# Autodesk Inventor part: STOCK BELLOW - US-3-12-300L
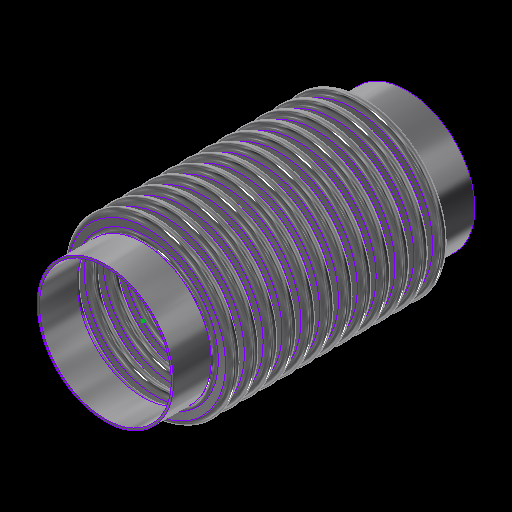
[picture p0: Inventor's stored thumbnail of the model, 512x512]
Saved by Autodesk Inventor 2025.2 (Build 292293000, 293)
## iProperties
Category: 22 GA (0.030 THICK)
RuleStatus: InUse
Created: 2024-01
Part Number: STOCK BELLOW - US-3-12-300L
Project: =STOCK BELLOWS: <Stock Number><SFILL>
Material: ASTM A240-304
Description: =STOCK BELLOWS: <Stock Number>, <SID_> I.D., <SOD_> O.D., <SPLY_> PLY, <Category>, <SNET_CONS> CONS.<PITCH_><STANGENT_> TANGENT<SFILL>
Document SubType Name: Sheet Metal
Designer: GS
Stock Number: U.S-3-12-300L
Surface Area: 2582.18 cm^2
Volume: 194.783 cm^3
Sheet Metal Rule: Default
Appearance: STAINLESS STEEL
Mass: 1569.42 g
Density: 8.05729 g/cm^3
THK: 0.036
ID: 3.500
OD: 4.250
CONS_: 2
PITCH: 0.500
TANGENT: 0.500
BELLOWS_UPSET: 0.000
d79: 1.000
d82: 1.000
d83: 26.000
d84: 24.000
d174: 8
d214: 8
STHK_: 0.030
SID_: 3.500
SOD_: 4.500
SPITCH_: 0.500
STANGENT__: 1.000
SBELLOWS_UPSET_: 0.000
SDIFF_TAN: 1.000
d252: 2
d275: 2
d287: 0.050
d289: 0.500
d290: 0.000
SOD_NECK: 3 5/8
PLY: 1
PSET: 4.178
PBAR: 1.035
COUNTER: 1.500
NET_TUBE: 3.071
CONS: 2
S_CONS: 0
NET_CONS: 2
ID_M: 88.90 mm
OD_M: 107.95 mm
THK_M: 0.91 mm
ID_U: 3.500 in
OD_U: 4.250 in
THK_U: 0.036 in
TANGENT2: 0.500
TAN_TO_TAN: 1.000 in
d80: 2.571
d81: 10
SID: 2.375
SCONS_: 12
SPITCH: 0.250
STANGENT_: 1.000
SBELLOWS_UPSET: 0.000
SNET_CONS: 12
SS_CONS: 0
SCONS: 8
d190: 8
d191: 1
d192: 1
d193: 8
d194: 0
SIZE: 3.00
PRESSURE: 300
d230: 8
STANGENT: 4.000
SPLY_: 2
d233: 8
d234: 0
d263: 2
d265: 1
d268: 2
d269: 0
d286: 2
d288: 1
d291: 2
d292: 0
SREROLL: 0.750
BLETP: 1.000 ul
PRES_Copy: 85
MATTABLE: 20 GA (0.036 THICK)
PART_NUMBER: U.S-3-12-300L
PITCH_: =, <SPITCH_> PITCH,
CFILL: .
SFILL: .
MESH: ,
COMP: 0.85
EXT: 0.43
LAT: 0.42
ANG: 573
ASR: 2820
LSR: 1880
ANSR: 98
PRES: 300
COMPM: 8.5
EXTM: 4.25
LATM: 4.20
ASRM: 493.867
PRESM: 20.684
LSRM: 329.244
ANSRM: 17.163
TEMPMIN: 20
TEMPMAX: 800
TEMPMINM: -7
TEMPMAXM: 427
WEIGHTM: 1.569
WEIGHT: 3.460
Author: GS
Keywords: 20 GA (0.036 THICK)
Comments: =STOCK BELLOW - <STOCK NUMBER>
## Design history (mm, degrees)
sketch "Sketch2"
  geometry: L1 (0, -177.245)-(0, 562.856) reference; L2 (45.364, 0)-(44.45, 0); L3 (48.082, -2.718)-(50.343, -2.718); L4 (48.082, -3.632)-(50.343, -3.632); L5 (50.343, -9.982)-(48.082, -9.982); L6 (50.343, -9.068)-(48.082, -9.068); L7 (45.364, -12.7)-(44.45, -12.7); L8 (48.082, 0)-(48.082, -12.7); L9 (50.343, -6.35)-(53.975, -6.35); L10 (44.45, 0)-(44.45, -12.7); L11 (20.376, 102.841)-(20.376, 101.926); L12 (58.262, 457.127)-(58.262, 349.177); L13 (58.262, 444.427)-(58.262, 336.477); L14 (93.133, -58.817)-(93.133, -71.517); L15 (118.746, -66.401)-(118.746, -66.401); L16 (50.343, -9.068)-(50.343, -9.982); L17 (48.082, -9.068)-(48.082, -9.982); L18 (48.082, -9.525)-(50.343, -9.525); L19 (53.975, 0)-(53.975, -12.7); L20 (-50.343, -9.068)-(-50.343, -9.982); L21 (-50.343, -2.718)-(-48.082, -2.718); L22 (-50.343, -3.632)-(-48.082, -3.632); L23 (-48.082, -9.068)-(-50.343, -9.068); L24 (-50.343, -9.525)-(-48.082, -9.525); L25 (-48.082, -9.982)-(-50.343, -9.982); L26 (-48.082, -9.068)-(-48.082, -9.982); L27 (-44.45, 0.653)-(-44.45, -12.047); L28 (-48.082, -6.35)-(-44.45, -6.35); L29 (-50.343, 0.653)-(-50.343, -12.7); L30 (-53.061, 0)-(-53.975, 0); L31 (-53.975, 0)-(-53.975, -12.7); L32 (-53.061, -12.7)-(-53.975, -12.7); A1 r 2.718 centre (48.082, 0) between (45.364, 0) and (48.082, -2.718); A2 r 3.632 centre (48.082, 0) between (44.45, 0) and (48.082, -3.632); A3 r 3.632 centre (50.343, -6.35) between (50.343, -9.982) and (50.343, -2.718); A4 r 2.718 centre (50.343, -6.35) between (50.343, -9.068) and (50.343, -3.632); A5 r 2.718 centre (48.082, -12.7) between (48.082, -9.982) and (45.364, -12.7); A6 r 3.632 centre (48.082, -12.7) between (48.082, -9.068) and (44.45, -12.7); A7 r 3.175 centre (50.343, -6.35) between (50.343, -9.525) and (53.518, -6.35); A8 r 3.175 centre (48.082, -12.7) between (48.082, -9.525) and (44.907, -12.7); A9 r 2.718 centre (-50.343, -12.7) between (-50.343, -9.982) and (-53.061, -12.7); A10 r 2.718 centre (-48.082, -6.35) between (-48.082, -9.068) and (-48.082, -3.632); A11 r 3.175 centre (-48.082, -6.35) between (-48.082, -9.525) and (-44.907, -6.35); A12 r 3.632 centre (-48.082, -6.35) between (-48.082, -9.982) and (-48.082, -2.718); A13 r 3.175 centre (-50.343, -12.7) between (-50.343, -9.525) and (-53.518, -12.7); A14 r 3.632 centre (-50.343, -12.7) between (-50.343, -9.068) and (-53.975, -12.7); A15 r 2.718 centre (-50.343, 0) between (-53.061, 0) and (-50.343, -2.718); A16 r 3.632 centre (-50.343, 0) between (-53.975, 0) and (-50.343, -3.632); 10 further points
  constraints: 62 end point, 38 point on circle, 20 tangent, 16 centre point, 12 parallel, 9 midpoint, 7 vertical, 6 coincident, 6 concentric, 6 point on line, 4 equal radius, 4 perpendicular, 3 horizontal, 1 collinear, 1 horizontal alignment, 10 other
  dimensions: "THK" = 0.9144 distance of L11.start L11.end; "ID" = 88.9 distance of L11.end point (20.376, 13.026); "OD" = 107.95 distance of L12.start L12.end; "PITCH" = 12.7 distance of L12.start L13.start; "TANGENT" = 12.7 distance of L14.start L14.end; "BELLOWS_UPSET" = 0 distance of L15.start L15.end; "d43" = 88.9 diameter of L10 L1 (= ID); "d44" = 107.95 diameter of L9.end L1 (= OD); "d45" = 0.9144 distance between parallel lines of L5 L6 (computed from THK, PLY); "d46" = 3.6322 radius of A3 (computed from PITCH, THK, PLY); "UPSET_PITCH" = 12.7 distance of L2.end L7.end (derived); "SIDEWALL_ANGLE" = 360 deg dimension on L3 L9 (derived); "CON_GAP" = 5.4356 distance of point (48.082, -9.068) point (48.082, -3.632) (derived); "TAN1" = 4.98728 dimension on A8 (derived); "TAN2" = 4.98728 dimension on A7 (derived); "LEG1" = 2.2606 distance of L18.start L18.end (derived); "d278" = 0.9144 distance between parallel lines of L25 L23 (derived); "d279" = 3.6322 radius of A12 (derived); "d280" = 12.7 distance of L30.end L31.end (derived); "d281" = 360 deg dimension on L21 L28 (derived); "d282" = 5.4356 distance of point (-50.343, -9.068) point (-50.343, -3.632) (derived); "d283" = 4.98728 dimension on A13 (derived); "d284" = 4.98728 dimension on A11 (derived); "d285" = 2.2606 distance of L24.start L24.end (derived); "d293" = 88.9 diameter of L27 L1 (derived); "d294" = 107.95 diameter of L31 L1 (derived)
  node "Sketch Rectangular Pattern1" dims "d31" = 25.4, "ID" = 88.9
  node "Sketch Rectangular Pattern2" dims "d39" = 25.4, "PITCH" = 12.7
revolve "CONS" stored, may be unused: angle "d48" = 90 deg
node "BELLOW MIDPLANE"
pattern_linear "Rectangular Pattern2" dims "d52" = 12.7 (= UPSET_PITCH)
sketch "Sketch5"
  geometry: C1 r 45.364 at (0, 0) reference; C2 r 44.45 at (0, 0) reference
extrude "TANGENT" new body sketch "Sketch5" distance "d53" = 12.7 (= TANGENT); taper "d54" = 0 deg
revolve "SAMETAN" stored, may be unused: angle "d65" = 90 deg
revolve "DIFFTAN" stored, may be unused: angle "d70" = 90 deg
sketch "Sketch9"
  geometry: L1 (53.319, 0)-(-53.319, 0) reference; L2 (0, -17.78)-(0, 17.78) reference; L3 (38.085, 0)-(-38.085, 0); L4 (38.085, -11.906)-(38.085, 11.906); L5 (25.385, -11.906)-(25.385, 11.906); L6 (13.15, 11.906)-(13.15, -11.906); L7 (-25.385, -11.906)-(-25.385, 11.906); L8 (-38.085, -11.906)-(-38.085, 11.906); L9 (37.291, -11.906)-(37.291, 11.906); L10 (38.085, -11.906)-(37.291, -11.906); L11 (38.085, 11.906)-(37.291, 11.906); L12 (13.546, 11.906)-(12.753, 11.906); L13 (12.753, 11.906)-(12.753, -11.906); L14 (12.753, -11.906)-(13.546, -11.906); L15 (13.546, -11.906)-(13.546, 11.906); L16 (-13.546, 11.906)-(-13.546, -11.906); L17 (-13.15, 11.906)-(-13.15, -11.906); L18 (-13.546, -11.906)-(-12.753, -11.906); L19 (-12.753, -11.906)-(-12.753, 11.906); L20 (-12.753, 11.906)-(-13.546, 11.906); L21 (-38.085, -11.906)-(-37.291, -11.906); L22 (-37.291, -11.906)-(-37.291, 11.906); L23 (-37.291, 11.906)-(-38.085, 11.906); L24 (-38.085, 11.906)-(-38.085, -11.906); L25 (38.085, -0.397)-(-38.085, -0.397); L26 (-38.085, -0.397)-(-38.085, 0.397); L27 (-38.085, 0.397)-(38.085, 0.397); L28 (38.085, 0.397)-(38.085, -0.397); L29 (-38.085, 11.906)-(38.085, 11.906); L30 (38.085, 11.906)-(38.085, 12.7); L31 (38.085, 12.7)-(-38.085, 12.7); L32 (-38.085, 12.7)-(-38.085, 11.906); L33 (38.085, -11.906)-(-38.085, -11.906); L34 (-38.085, -11.906)-(-38.085, -12.7); L35 (-38.085, -12.7)-(38.085, -12.7); L36 (38.085, -12.7)-(38.085, -11.906); 30 further points
  constraints: 68 end point, 13 midpoint, 13 parallel, 8 horizontal, 7 perpendicular, 6 equal length, 3 point on line, 2 vertical, 14 other
  dimensions: "d115" = 23.8125 distance of L4.start L4.end (derived); "d116" = 12.7 distance between parallel lines of L4 L5 (derived); "d117" = 12.23516 distance between parallel lines of L5 L6 (derived); "d125" = 38.53427 distance between parallel lines of L7 L6 (derived); "d127" = 12.7 distance between parallel lines of L8 L7 (derived); "d128" = 24.93516 distance between parallel lines of L6 L4 (derived); "d130" = 76.16943 distance between parallel lines of L8 L4 (derived); "RULER_THK" = 0.79375 distance between parallel lines of L4 L9; "d135" = 0.79375 distance of L13.end L14.end (derived); "d138" = 26.29911 distance of L13.end L16.end (derived); "d143" = 0.79375 distance of L22.end L8.end (derived); "d144" = 0.79375 distance between parallel lines of L27 L25 (derived)
extrude "RULER" join sketch "Sketch9" distance "d149" = 0.79375 (derived); taper "d150" = 0 deg
extrude "BARS" join sketch "Sketch9" distance "d151" = 0.79375 (derived); taper "d152" = 0 deg
pattern_linear "Rectangular Pattern4" dims "d155" = 26.29911 (derived)
sketch "Sketch13"
  geometry: L1 (93.149, -52.467)-(93.149, -77.867); L2 (45.974, 0)-(44.45, 0); L3 (45.974, -12.7)-(44.45, -12.7); L4 (53.213, -10.287)-(48.387, -10.287); L5 (53.213, -8.763)-(48.387, -8.763); L6 (53.213, -6.35)-(57.15, -6.35); L7 (48.387, -2.413)-(53.213, -2.413); L8 (48.387, 0)-(48.387, -12.7); L9 (44.45, 0)-(44.45, -12.7); L10 (58.254, -382.131)-(58.254, -496.431); L11 (58.254, -394.831)-(58.254, -509.131); L12 (58.254, -420.231)-(58.254, -534.531); L13 (58.254, -432.931)-(58.254, -547.231); L14 (58.254, -445.631)-(58.254, -559.931); L15 (58.254, -458.331)-(58.254, -572.631); L16 (58.254, -471.031)-(58.254, -585.331); L17 (58.254, -407.531)-(58.254, -521.831); L18 (20.376, 102.688)-(20.376, 101.926); L19 (48.387, -3.937)-(53.213, -3.937); L20 (0, -722.935)-(0, 240.292) reference; L21 (-23.752, 0)-(142.514, 0) reference; A1 r 2.413 centre (48.387, 0) between (45.974, 0) and (48.387, -2.413); A2 r 2.413 centre (48.387, -12.7) between (48.387, -10.287) and (45.974, -12.7); A3 r 3.937 centre (48.387, -12.7) between (48.387, -8.763) and (44.45, -12.7); A4 r 2.413 centre (53.213, -6.35) between (53.213, -8.763) and (53.213, -3.937); A5 r 3.937 centre (53.213, -6.35) between (53.213, -10.287) and (53.213, -2.413); A6 r 3.937 centre (48.387, 0) between (44.45, 0) and (48.387, -3.937); 6 further points; 1 other entity
  constraints: 38 end point, 15 point on circle, 9 tangent, 6 centre point, 6 parallel, 5 vertical alignment, 4 point on line, 4 vertical, 3 coincident, 3 concentric, 2 collinear, 2 equal radius, 1 horizontal, 1 perpendicular, 23 other
  dimensions: "SBELLOWS_UPSET_" = 0 distance of point (118.762, -66.401) point (118.762, -66.401); "STOTAL_THK_BELLOW__" = 1.524 distance between parallel lines of L4 L5 (derived); "d224" = 3.937 radius of A5 (derived); "d225" = 12.7 distance of L2.end L3.end (derived); "SSIDEWALL_ANGLE_" = 0 deg angle of L7 L6 (derived); "SSCON_GAP_" = 4.826 distance of point (48.387, -8.763) point (48.387, -3.937) (derived); "d235" = 88.9 diameter of L9 L20 (derived); "d236" = 114.3 diameter of L6.end L20 (derived)
  node "Sketch Rectangular Pattern4" dims "d228" = 25.4
  node "Sketch Rectangular Pattern5" dims "d229" = 25.4
revolve "SBELLOW" stored, may be unused: angle "d197" = 90 deg
pattern_linear "Rectangular Pattern5" dims "d204" = 12.7 (derived)
revolve "STANGENT" stored, may be unused: angle "d240" = 90 deg
revolve "SSAMETAN" stored, may be unused: angle "d241" = 90 deg
revolve "SDIFFTAN" stored, may be unused: angle "d246" = 90 deg
revolve "INVCON" stored, may be unused: angle "d295" = 90 deg
pattern_linear "Rectangular Pattern6" dims "d298" = 12.7 (derived)
revolve "INVTANGENT" stored, may be unused: angle "d302" = 90 deg
revolve "INVSAMETAN" stored, may be unused: angle "d307" = 90 deg
revolve "INVDIFFTAN" stored, may be unused: angle "d312" = 90 deg
sketch "ID BELLOW MOUNT CALC"
  geometry: L1 (44.45, 0)-(38.1, 0); L2 (38.1, 0)-(38.1, 12.7); L3 (38.1, 12.7)-(44.45, 12.7); L4 (44.45, 12.7)-(44.45, 0); L5 (36.513, 12.7)-(35.598, 12.7); L6 (35.598, 12.7)-(35.598, 0); L7 (35.598, 0)-(36.513, 0); L8 (36.513, 0)-(36.513, 12.7); L9 (0, -2.54)-(0, 15.24) reference; L10 (-8.89, 0)-(53.34, 0) reference; 1 further point
  constraints: 16 end point, 5 parallel, 2 collinear, 2 horizontal, 2 perpendicular
  dimensions: "d314" = 12.7 distance of L5.end L6.end (derived); "d315" = 0.9144 distance of L5.start L5.end (derived); "IG" = 1.5875 distance between parallel lines of L2 L8; "PIPE_OD" = 88.9 diameter of L4 L9; "PIPE_WALL" = 6.35 distance of L2.end L3.end; "ID_MT_BELLOW" = 71.1962 diameter of L6 L9 (derived)
revolve "CFILL" stored, may be unused: angle "d320" = 90 deg
pattern_linear "Rectangular Pattern7" dims "d323" = 12.7 (derived)
revolve "SFILL" stored, may be unused: angle "d324" = 90 deg
pattern_linear "Rectangular Pattern8" dims "d327" = 12.7 (derived)
node "STOCK BELLOW MIDPLANE"
node "BELLOW"
sketch "Sketch6"
  geometry: L1 (-12.7, 45.364)-(0, 45.364); L2 (0, 45.364)-(0, 44.45); L3 (0, 44.45)-(-12.7, 44.45); L4 (-12.7, 44.45)-(-12.7, 45.364); L5 (10.16, 0)-(-60.96, 0) reference; L6 (-38.1, -89.422)-(-38.1, 153.44) reference; 1 further point
  constraints: 8 end point, 2 parallel, 1 horizontal, 1 perpendicular
  dimensions: "d61" = 12.7 distance of L2.end L3.end (derived); "d62" = 0.9144 distance of L1.end L2.end (derived); "d63" = 88.9 diameter of L3 L5 (derived); "d64" = 25.4 distance between parallel lines of L4 L6 (derived)
sketch "Sketch12"
  geometry: 1 further point
sketch "Sketch14"
  geometry: L1 (-25.4, 45.974)-(0, 45.974); L2 (0, 45.974)-(0, 44.45); L3 (0, 44.45)-(-25.4, 44.45); L4 (-25.4, 44.45)-(-25.4, 45.974); L5 (5.08, 0)-(-30.48, 0) reference; L6 (0, -9.195)-(0, 55.169) reference; 1 further point
  constraints: 8 end point, 2 parallel, 1 collinear, 1 horizontal, 1 perpendicular
  dimensions: "d237" = 1.524 distance of L3.end L1.start (derived); "d238" = 88.9 diameter of L3 L5 (derived); "d239" = 25.4 distance of L1.start L1.end (derived); "SOD_NECK" = 91.948 diameter of L1 L5 (derived)
sketch "Sketch15"
  geometry: L1 (-9.195, 0)-(55.169, 0) reference; L2 (44.45, -152.4)-(45.974, -152.4); L3 (45.974, -152.4)-(45.974, -177.8); L4 (45.974, -177.8)-(44.45, -177.8); L5 (44.45, -177.8)-(44.45, -152.4); L6 (0, -215.9)-(0, 50.8) reference; 1 further point
  constraints: 8 end point, 2 parallel, 1 horizontal, 1 perpendicular
  dimensions: "d205" = 25.4 distance of L4.end L2.start (derived); "d206" = 1.524 distance of L3.end L4.end (derived); "d207" = 88.9 diameter of L5 L6 (derived); "d208" = 152.4 distance between parallel lines of L1 L2 (derived)
node "TANGENT_"
node "SAME_TAN"
sketch "Sketch8"
  geometry: L1 (45.364, -25.4)-(44.45, -25.4); L2 (44.45, -25.4)-(44.45, -38.1); L3 (44.45, -38.1)-(45.364, -38.1); L4 (45.364, -38.1)-(45.364, -25.4); L5 (0, -48.26)-(0, 22.86) reference; L6 (-89.422, 0)-(153.44, 0) reference; 1 further point
  constraints: 8 end point, 2 parallel, 1 horizontal, 1 perpendicular
  dimensions: "d66" = 88.9 diameter of L2 L5 (derived); "TOTAL_THK_BELLOW" = 0.9144 distance of L2.end L3.end (derived); "d68" = 25.4 distance between parallel lines of L1 L6 (derived); "d69" = 12.7 distance of L1.end L2.end (derived)
node "DIFF_TAN"
node "Sketch Rectangular Pattern3" dims "d138" = 26.29911 (derived), "d141" = 25.4
node "SBELLOW_"
node "STANGENT_"
node "SSAME_TAN"
sketch "Sketch16"
  geometry: L1 (45.974, -152.4)-(44.45, -152.4); L2 (44.45, -152.4)-(44.45, -177.8); L3 (44.45, -177.8)-(45.974, -177.8); L4 (45.974, -177.8)-(45.974, -152.4); L5 (0, -215.9)-(0, 50.8) reference; L6 (-9.195, 0)-(55.169, 0) reference; 1 further point
  constraints: 8 end point, 2 parallel, 1 horizontal, 1 perpendicular
  dimensions: "SDIFF_TAN" = 25.4 distance of L3.end L1.start; "d243" = 1.524 distance of L2.end L3.end (derived); "d244" = 152.4 distance between parallel lines of L1 L6 (derived); "d245" = 88.9 diameter of L2 L5 (derived)
node "SDIFF_TAN"
body "Solid15"
sketch "Sketch17"
  geometry: L1 (53.975, 12.7)-(53.061, 12.7); L2 (53.061, 12.7)-(53.061, 0); L3 (53.061, 0)-(53.975, 0); L4 (53.975, 0)-(53.975, 12.7); L5 (0, -2.54)-(0, 15.24) reference; L6 (-10.795, 0)-(64.77, 0) reference; 2 further points
  constraints: 8 end point, 2 parallel, 1 horizontal, 1 midpoint, 1 perpendicular, 1 point on line
  dimensions: "INVTANGENT" = 12.7 distance of L3.end L1.start (derived); "d300" = 0.9144 distance of L1.start L1.end (derived); "d301" = 107.95 diameter of L4 L5 (derived)
body "Solid16"
sketch "Sketch18"
  geometry: L1 (53.975, -25.4)-(53.061, -25.4); L2 (53.061, -25.4)-(53.061, -38.1); L3 (53.061, -38.1)-(53.975, -38.1); L4 (53.975, -38.1)-(53.975, -25.4); L5 (-10.795, 0)-(64.77, 0) reference; L6 (0, -48.26)-(0, 22.86) reference; 1 further point
  constraints: 8 end point, 2 parallel, 1 horizontal, 1 perpendicular
  dimensions: "d303" = 25.4 distance between parallel lines of L1 L5 (derived); "d304" = 12.7 distance of L3.end L1.start (derived); "d305" = 0.9144 distance of L2.end L3.end (derived); "d306" = 107.95 diameter of L4 L6 (derived)
body "Solid17"
sketch "Sketch19"
  geometry: L1 (53.975, -25.4)-(53.061, -25.4); L2 (53.061, -25.4)-(53.061, -38.1); L3 (53.061, -38.1)-(53.975, -38.1); L4 (53.975, -38.1)-(53.975, -25.4); L5 (0, -48.26)-(0, 22.86) reference; L6 (-10.795, 0)-(64.77, 0) reference; 1 further point
  constraints: 8 end point, 2 parallel, 1 horizontal, 1 perpendicular
  dimensions: "d308" = 12.7 distance of L1.end L2.end (derived); "d309" = 107.95 diameter of L4 L5 (derived); "d310" = 0.9144 distance of L2.end L3.end (derived); "d311" = 25.4 distance between parallel lines of L1 L6 (derived)
body "Solid18"
body "Solid19"
body "Solid20"
other parameters: "BMPL" = -76.2, "PSET" = 106.1212 (computed from OD, THK, PLY) [user parameter], "PBAR" = 26.29911 (= 0.570796 x PITCH + OD - ID) [user parameter; used in 1 equation term], "COUNTER" = 15 [user parameter], "NET_TUBE" = 77.99823 (computed from CONS_, PBAR, TANGENT) [user parameter], "S_CONS" = 0 [user parameter; used in 1 equation term], "ID_M" = 88.9 (= ID) [user parameter], "OD_M" = 107.95 (= OD) [user parameter], "THK_M" = 0.9144 (= THK) [user parameter], "ID_U" = 88.9 (= ID) [user parameter], "OD_U" = 107.95 (= OD) [user parameter], "THK_U" = 0.9144 (= THK) [user parameter], "D_UNITS" = 0 [user parameter], "TANGENT2" = 12.7 [user parameter], "TAN_TO_TAN" = 25.4 [user parameter], "OD_NECK" = 90.7288 [user parameter], "d79" = 25.4, "d80" = 65.29823 [user parameter], "d82" = 25.4, "d83" = 660.4, "d84" = 609.6, "sa_0" = 4, "FRAME_THK" = 0.79375 [user parameter], "CON_FLAT" = 12.23516 [user parameter], "SID" = 60.325 [user parameter], "SPITCH" = 6.35 [user parameter], "STANGENT_" = 25.4 [user parameter], "SBELLOWS_UPSET" = 0 [user parameter], "SS_CONS" = 0 [user parameter], "STAN_TO_TAN_" = 152.4 [user parameter], "d100" = 1.524 [user parameter], "d191" = 25.4 [user parameter], "d194" = 0 [user parameter], "STANGENT" = 101.6 [user parameter], "d234" = 0 [user parameter], "SUPSET_PITCH_" = 12.7 [user parameter], "d269" = 0 [user parameter], "d287" = 1.27, "d289" = 12.7, "d290" = 0, "d292" = 0 [user parameter], "Thickness" = 3.048 (derived), "KFactor" = 4.4, "BendRadius" = 3.048 (derived), "BendReliefWidth" = 3.048 (derived), "BendReliefDepth" = 1.524 (derived), "CornerReliefSize" = 12.192 (derived), "SeamGap" = 0.00508, "MinimumRemnant" = 6.096 (derived), "TransitionRadius" = 3.048 (derived), "JacobiRadiusSize" = 3.048 (derived), "GapSize" = 3.048 (derived), "SREROLL" = 19.05 [user parameter], "CUR_STK_PITCH" = 12.7 [user parameter], "d328" = -76.2 (derived), "ASR" = 28200 [user parameter], "LSR" = 18800 [user parameter], "BLETP" = 1 [user parameter], "ASRM" = 4938.666 [user parameter], "PRESM" = 206.83949 [user parameter], "LSRM" = 3292.444 [user parameter], "ANSRM" = 171.6274 [user parameter], "TEMPMIN" = 2664.83333 [user parameter], "TEMPMAX" = 6998.16667 [user parameter], "TEMPMINM" = 2664.83333 [user parameter], "TEMPMAXM" = 6998.16667 [user parameter], "WEIGHT" = 15.69419 [user parameter], "WEIGHTM" = 0.01569 [user parameter]
